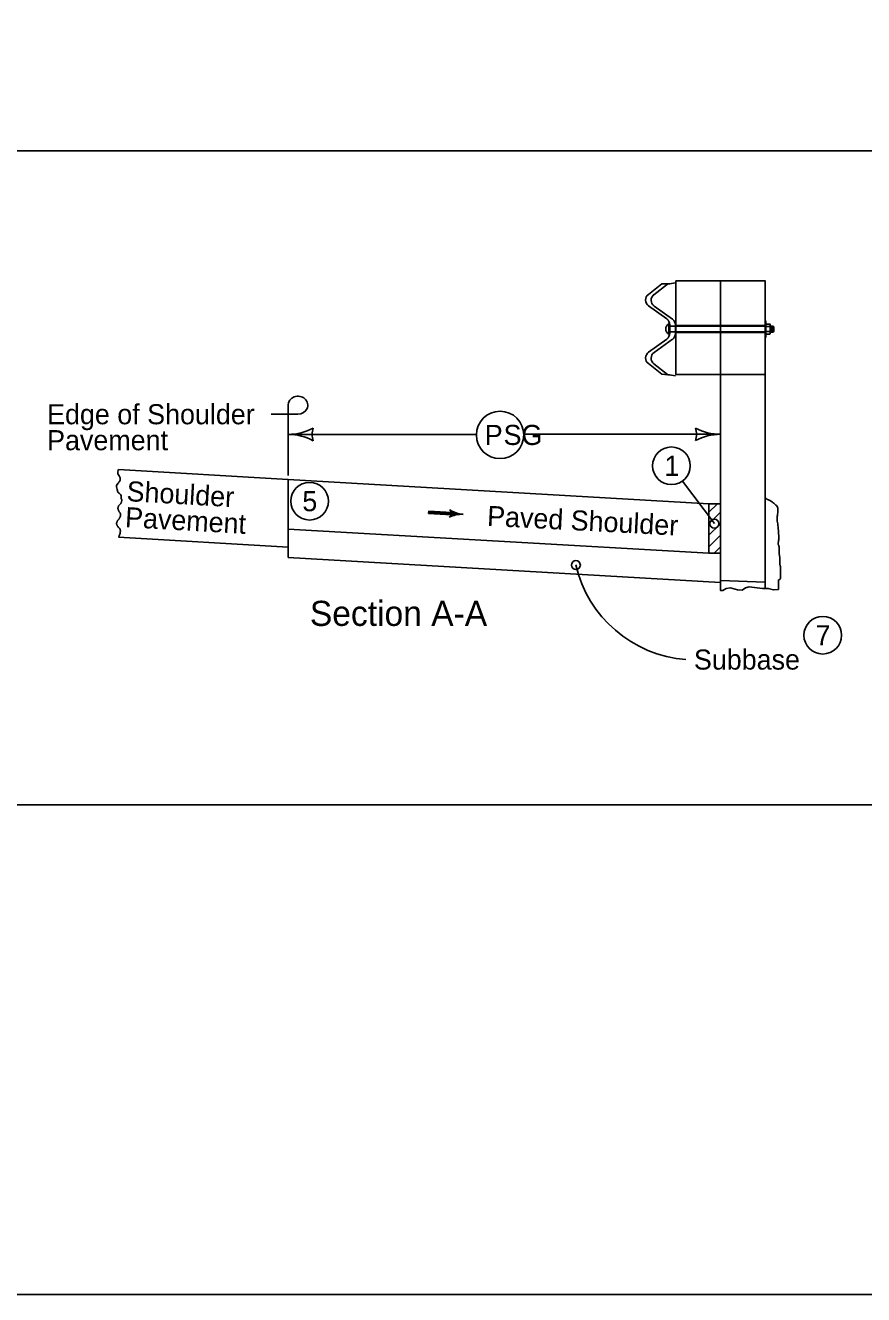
# Model space of a CAD drawing. Extents: x 8045 to 81668, y 6217 to 16762.
# Drawn here: x 10335 to 11002, y 7924 to 8935 of the extents above; entities that cross this region are included whole.
import ezdxf

# ---------------------------------------------------------------- set-up
doc = ezdxf.new("R2010")
doc.units = 0
for name, color, linetype in [('dsnStdDetailExtension', 7, 'Continuous'), ('dsnStdDimension', 7, 'Continuous'), ('dsnStdLabel', 7, 'Continuous'), ('dsnStdLineWork', 7, 'Continuous'), ('dsnStdPattern', 7, 'Continuous'), ('dsnStdSection', 7, 'Continuous'), ('Level 4', 7, 'Continuous'), ('Level 8', 7, 'Continuous'), ('TextBlockOut', 7, 'Continuous')]:
    doc.layers.add(name, color=color, linetype=linetype)

msp = doc.modelspace()

# ---------------------------------------------------------------- linework, layer by layer
at = {"layer": 'dsnStdDetailExtension'}
msp.add_circle((10773.3, 8505.4), 3.54, dxfattribs=at)
msp.add_circle((10773.3, 8505.4), 3.54, dxfattribs=at)
at = {"layer": 'dsnStdDimension'}
msp.add_line((10152.2, 8314.4), (13247.9, 8314.4), dxfattribs=at)
at = {"layer": 'dsnStdLabel'}
for p, q in [((10831, 8721.1), (10841.8, 8729.5)), ((10835.4, 8720.8), (10846.2, 8729.3)), ((10841.8, 8729.5), (10848.1, 8729.6)), ((10846.2, 8729.3), (10852.6, 8730.4)), ((10924.1, 8731.8), (10853, 8731.8)), ((10853, 8657.2), (10853, 8731.8)), ((10888.5, 8657.2), (10888.5, 8731.8)), ((10924.1, 8731.8), (10924.1, 8486.8)), ((10845.7, 8701.5), (10831.2, 8712)), ((10850.2, 8701.3), (10835.6, 8711.8)), ((10924.1, 8700.1), (10924.7, 8700.1)), ((10924.7, 8686.8), (10924.7, 8700.1)), ((10847.3, 8689.4), (10847.3, 8697.5)), ((10847.3, 8695.8), (10852.8, 8695.8)), ((10847.3, 8691.2), (10853, 8691.2)), ((10848.1, 8690.1), (10848.1, 8696.9)), ((10848.1, 8690.1), (10848.1, 8693.5)), ((10848.1, 8693.5), (10848.1, 8690.1)), ((10848.3, 8695.8), (10853, 8695.8)), ((10852.6, 8693.3), (10852.6, 8696.7)), ((10852.6, 8689.9), (10852.6, 8693.3)), ((10852.6, 8693.3), (10852.6, 8689.9)), ((10853, 8696.2), (10924.1, 8696.2)), ((10853, 8695.8), (10924.1, 8695.8)), ((10853, 8691.2), (10924.1, 8691.2)), ((10853, 8690.8), (10924.1, 8690.8)), ((10924.7, 8697.5), (10927.7, 8697.5)), ((10924.7, 8695.5), (10927.7, 8695.5)), ((10924.7, 8691.4), (10927.7, 8691.4)), ((10924.7, 8689.4), (10927.7, 8689.4)), ((10928.1, 8690.4), (10928.1, 8696.5)), ((10928.1, 8695.8), (10930.4, 8695.8)), ((10928.1, 8691.1), (10930.4, 8691.1)), ((10929, 8695.8), (10929, 8691.1)), ((10929.7, 8695.8), (10929.7, 8691.1)), ((10930.4, 8695.8), (10930.9, 8695.3)), ((10930.4, 8695.8), (10930.4, 8691.1)), ((10930.9, 8691.7), (10930.4, 8691.1)), ((10930.9, 8695.3), (10930.9, 8691.7)), ((10831.2, 8675.1), (10845.7, 8685.5)), ((10835.6, 8674.8), (10850.2, 8685.3)), ((10924.1, 8686.8), (10924.7, 8686.8)), ((10841.8, 8657.5), (10831, 8665.9)), ((10846.2, 8657.3), (10835.4, 8665.7)), ((10848.9, 8656.8), (10841.8, 8657.5)), ((10852.6, 8656.2), (10846.2, 8657.3)), ((10888.5, 8657.2), (10853, 8657.2)), ((10888.5, 8657.2), (10888.5, 8485)), ((10409, 8581.6), (10544.1, 8573.7)), ((10544.1, 8573.7), (10544.1, 8519.7)), ((10544.1, 8573.7), (10879.2, 8554.2)), ((10879.2, 8547.5), (10886, 8554.2)), ((10879.2, 8547.5), (10886, 8554.2)), ((10879.2, 8547.5), (10886, 8554.2)), ((10879.2, 8547.5), (10886, 8554.2)), ((10879.2, 8554.2), (10888.5, 8554.2)), ((10879.2, 8554.2), (10879.2, 8514.8)), ((10879.2, 8538.3), (10888.5, 8547.5)), ((10879.2, 8538.3), (10888.5, 8547.5)), ((10879.2, 8538.3), (10888.5, 8547.5)), ((10879.2, 8538.3), (10888.5, 8547.5)), ((10934.1, 8547.5), (10934.1, 8547.5)), ((10879.2, 8529.1), (10888.5, 8538.3)), ((10879.2, 8529.1), (10888.5, 8538.3)), ((10879.2, 8529.1), (10888.5, 8538.3)), ((10879.2, 8529.1), (10888.5, 8538.3)), ((10409, 8527.6), (10544.1, 8519.7)), ((10879.2, 8514.8), (10544.1, 8534.1)), ((10879.2, 8519.8), (10888.5, 8529.1)), ((10544.1, 8519.7), (10544.1, 8511.3)), ((10883.3, 8514.8), (10888.5, 8519.9)), ((10544.1, 8511.3), (10888.5, 8491.4)), ((10879.2, 8514.8), (10888.5, 8514.8))]:
    msp.add_line(p, q, dxfattribs=at)
for points in [[(10927.8, 8695.5), (10927.8, 8695.5), (10927.9, 8695.6), (10928, 8695.9), (10928, 8696.1), (10928, 8694.2), (10928, 8694.7), (10927.9, 8695.1), (10927.8, 8695.4), (10927.8, 8695.5), (10927.8, 8695.5), (10927.9, 8695.6), (10928, 8695.9), (10928, 8696), (10928, 8694.5), (10928, 8695), (10927.9, 8695.2), (10927.8, 8695.5), (10927.8, 8695.5), (10928, 8695.7), (10928, 8695.9), (10928, 8694.7), (10927.8, 8695.5), (10928, 8695.7), (10928, 8694.9), (10927.8, 8695.4), (10928, 8695.7), (10928, 8695), (10927.9, 8695.4), (10928, 8695.6), (10928, 8695.2), (10927.9, 8695.4), (10927.9, 8695.5), (10927.9, 8695.3), (10927.9, 8695.4), (10927.9, 8695.4)], [(10928, 8690.8), (10928, 8691), (10928, 8691.2), (10927.9, 8691.4), (10927.8, 8691.5), (10927.8, 8691.5), (10927.9, 8691.8), (10928, 8692.1), (10928.1, 8692.8), (10928, 8690.8), (10928, 8690.9), (10928, 8691.1), (10927.9, 8691.3), (10927.8, 8691.4), (10927.8, 8691.5), (10927.9, 8691.7), (10928, 8692.2), (10928, 8692.6), (10928, 8691), (10928, 8691.1), (10928, 8691.2), (10927.8, 8691.4), (10927.9, 8691.6), (10928, 8691.9), (10928, 8692.3), (10928, 8691.1), (10928, 8691.2), (10927.9, 8691.4), (10927.9, 8691.6), (10928, 8691.9), (10928, 8692.1), (10928, 8691.2), (10927.9, 8691.3), (10927.9, 8691.4), (10928, 8691.9), (10928, 8691.3), (10927.9, 8691.4), (10927.9, 8691.7), (10927.9, 8691.4), (10927.9, 8691.4), (10927.9, 8691.5), (10927.9, 8691.5)], [(10934.6, 8523.6), (10934.5, 8523.3), (10934.5, 8523.1), (10934.5, 8523), (10934.5, 8522.8), (10934.5, 8522.6), (10934.5, 8522.4), (10934.5, 8522.1), (10934.5, 8521.9), (10934.6, 8521.6), (10934.7, 8521.3), (10934.9, 8521.1), (10934.9, 8520.9), (10935, 8520.7), (10935, 8520.5), (10935, 8520.3), (10935.1, 8520.2), (10935.1, 8520), (10935.1, 8519.8), (10935.1, 8519.6), (10935.1, 8519.4), (10935.1, 8519.2), (10935.1, 8518.9), (10935.1, 8518.7), (10935.1, 8518.5), (10935.1, 8518.2), (10935.1, 8518), (10935.1, 8517.8), (10935.2, 8517.7), (10935.2, 8517.5), (10935.2, 8517.3), (10935.2, 8517.1), (10935.2, 8516.9), (10935.2, 8516.7), (10935.2, 8516.5), (10935.2, 8516.3), (10935.2, 8516.1), (10935.2, 8515.9), (10935.2, 8515.7), (10935.2, 8515.5), (10935.2, 8515.3), (10935.2, 8515.1), (10935.2, 8514.9), (10935.2, 8514.7), (10935.2, 8514.6), (10935.2, 8514.4), (10935.2, 8514.2), (10935.3, 8514.1), (10935.3, 8513.9), (10935.3, 8513.7), (10935.4, 8513.6), (10935.4, 8513.4), (10935.4, 8513.2), (10935.5, 8513.1), (10935.5, 8512.9), (10935.5, 8512.7), (10935.5, 8512.5), (10935.5, 8512.2), (10935.6, 8511.9), (10935.6, 8511.7), (10935.6, 8511.5), (10935.6, 8511.3), (10935.6, 8511.1), (10935.6, 8510.9), (10935.6, 8510.7), (10935.6, 8510.5), (10935.6, 8510.4), (10935.6, 8510.2), (10935.6, 8510), (10935.6, 8509.8), (10935.6, 8509.6), (10935.6, 8509.4), (10935.6, 8509.2), (10935.6, 8509), (10935.6, 8508.8), (10935.6, 8508.6), (10935.6, 8508.4), (10935.6, 8508.2), (10935.6, 8508), (10935.6, 8507.8), (10935.6, 8507.6), (10935.6, 8507.4), (10935.6, 8507.2), (10935.6, 8507), (10935.6, 8506.8), (10935.6, 8506.6), (10935.6, 8506.4), (10935.6, 8506.2), (10935.7, 8506.1), (10935.7, 8505.9), (10935.7, 8505.7), (10935.8, 8505.5), (10935.9, 8505.2), (10935.9, 8505), (10936, 8504.9), (10936, 8504.7), (10936.1, 8504.6), (10936.2, 8504.5), (10936.2, 8504.3), (10936.2, 8504.1), (10936.2, 8503.9), (10936.3, 8503.8), (10936.3, 8503.6), (10936.3, 8503.4), (10936.3, 8503.2), (10936.3, 8503), (10936.3, 8502.8), (10936.3, 8502.6), (10936.3, 8502.4), (10936.3, 8502.2), (10936.3, 8502), (10936.3, 8501.9), (10936.3, 8501.7), (10936.3, 8501.5), (10936.3, 8501.3), (10936.3, 8501.1), (10936.3, 8500.9), (10936.3, 8500.7), (10936.3, 8500.5), (10936.3, 8500.3), (10936.3, 8500.1), (10936.3, 8499.9), (10936.3, 8499.7), (10936.3, 8499.5), (10936.3, 8499.3), (10936.3, 8499.1), (10936.3, 8498.9), (10936.3, 8498.9), (10936.3, 8499.2), (10936.3, 8499.4), (10936.3, 8499.6), (10936.3, 8499.4), (10936.3, 8499.2), (10936.3, 8499), (10936.3, 8498.8), (10936.3, 8498.6), (10936.3, 8498.4), (10936.3, 8498.2), (10936.3, 8498), (10936.3, 8497.8), (10936.3, 8497.6), (10936.3, 8497.5), (10936.3, 8497.3), (10936.3, 8497.1), (10936.3, 8496.9), (10936.3, 8496.7), (10936.2, 8496.6), (10936.2, 8496.4), (10936.2, 8496.2), (10936.2, 8496), (10936.2, 8495.8), (10936.2, 8495.6), (10936.2, 8495.4), (10936.2, 8495.2), (10936.2, 8495), (10936.2, 8494.8), (10936.2, 8494.6), (10936.1, 8494.5), (10936, 8494.3), (10935.9, 8494.2), (10935.8, 8494.1), (10935.7, 8494), (10935.5, 8493.9), (10935.3, 8493.9), (10935.2, 8493.8), (10935.1, 8493.7), (10935, 8493.6), (10934.8, 8493.5), (10934.7, 8493.4), (10934.7, 8493.3), (10934.6, 8493.2), (10934.6, 8493), (10934.6, 8492.8), (10934.6, 8492.6), (10934.6, 8485.8)], [(10934.7, 8485.8), (10930.6, 8485.6), (10926.5, 8486.8), (10921.9, 8486.8), (10917.7, 8487.2), (10911.4, 8488), (10908.3, 8487.3), (10905.7, 8485.5), (10902, 8485.7), (10896.4, 8487.3), (10893.1, 8486.8), (10890.3, 8485.2), (10888.5, 8485)]]:
    msp.add_lwpolyline(points, dxfattribs=at)
for centre, radius, start, end in [((10834.5, 8716.6), 5.68, 127.75, 234.6909), ((10838.9, 8716.4), 5.68, 127.75, 234.6909), ((10842.4, 8696.9), 5.68, 360, 54.691), ((10846.9, 8696.7), 5.68, 360, 54.691), ((10849.4, 8693.5), 4.54, 117.2029, 242.8461), ((10842.4, 8690.1), 5.68, 305.309, 0), ((10846.9, 8689.9), 5.68, 305.309, 0), ((10834.5, 8670.4), 5.68, 125.3091, 232.25), ((10838.9, 8670.2), 5.68, 125.3091, 232.25)]:
    msp.add_arc(centre, radius, start, end, dxfattribs=at)
for centre in [(10927.7, 8696.5), (10927.7, 8690.4)]:
    msp.add_ellipse(centre, major_axis=(0, -1.01), ratio=0.362258, start_param=6.283156, end_param=9.424748, dxfattribs=at)
for points in [[(10409, 8581.6), (10408.5, 8578), (10409.5, 8576.5), (10410.4, 8574.2), (10409.8, 8572.1), (10407.9, 8569.7), (10407.3, 8567.8), (10407.9, 8565.5), (10408.7, 8563.2), (10409.8, 8562.4), (10411.2, 8559.9), (10411.1, 8559.1)], [(10409.2, 8542), (10409.4, 8542.2), (10409.6, 8542.5), (10409.9, 8543), (10410.2, 8543.6), (10410.3, 8543.9), (10410.4, 8544.2), (10410.6, 8544.9), (10410.6, 8545.5), (10410.6, 8546.1), (10410.5, 8546.3), (10410.5, 8546.5), (10410.4, 8546.6), (10410.2, 8547), (10409.9, 8547.4), (10409.6, 8547.7), (10409.4, 8548.1), (10409.3, 8548.4), (10409.1, 8548.7), (10408.9, 8549.3), (10408.7, 8549.8), (10408.6, 8550.1), (10408.5, 8550.4), (10408.5, 8550.5), (10408.5, 8550.7), (10408.7, 8551.4), (10408.9, 8552), (10409.1, 8552.5), (10409.6, 8553.1), (10410.1, 8553.7), (10410.6, 8554.2), (10410.8, 8554.5), (10411, 8554.8), (10411.2, 8555.3), (10411.4, 8555.8), (10411.5, 8556.3), (10411.5, 8556.5), (10411.6, 8556.6), (10411.6, 8556.7), (10411.5, 8557.3), (10411.4, 8557.8), (10411.3, 8557.9), (10411.3, 8558), (10411.2, 8558.2), (10411.2, 8558.3), (10411.1, 8559.1)], [(10934.6, 8523.6), (10934.9, 8526.5), (10934.7, 8531.4), (10934.2, 8537.1), (10933.6, 8541.6), (10933.8, 8544.9), (10934.2, 8549.1), (10933.6, 8552.2), (10931.4, 8554.2), (10929.4, 8555.9), (10927.2, 8557), (10924.9, 8558.4), (10924.1, 8559)], [(10409.2, 8542), (10409, 8541.7), (10408.7, 8541.5), (10408.5, 8541.2), (10408.3, 8541), (10408.2, 8540.7), (10408, 8540.4), (10407.8, 8539.8), (10407.7, 8539.6), (10407.6, 8539.3), (10407.5, 8539), (10407.5, 8538.8), (10407.4, 8538.7), (10407.4, 8538.2), (10407.6, 8537.7), (10407.8, 8537.1), (10408, 8536.6), (10408.5, 8536), (10409, 8535.4), (10409.5, 8534.9), (10409.8, 8534.6), (10410, 8534.2), (10410.4, 8533.3), (10410.5, 8532.8), (10410.5, 8532.3), (10410.4, 8532.1), (10410.4, 8531.8), (10410.3, 8531.5), (10410.3, 8531.2), (10410, 8530.1), (10409.8, 8529.4), (10409.6, 8528.8), (10409.4, 8528.3), (10409.2, 8528), (10409.1, 8527.7), (10409, 8527.6)]]:
    msp.add_spline(points, degree=3, dxfattribs=at)
at = {"layer": 'dsnStdLineWork'}
for p, q in [((10544.1, 8612.8), (10544.1, 8633.7)), ((10530.7, 8625.6), (10539.4, 8625.6)), ((10551.9, 8625.6), (10539.4, 8625.6)), ((10544.1, 8576.9), (10544.1, 8612.8)), ((10544.1, 8609.5), (10693.9, 8609.5)), ((10731.8, 8609.6), (10888.5, 8609.6)), ((10674.3, 8546.4), (10656.1, 8547.4)), ((10674.3, 8547.4), (10674.3, 8547.4)), ((10674.2, 8545.4), (10674.2, 8545.4))]:
    msp.add_line(p, q, dxfattribs=at)
for points in [[(10674.3, 8547.3), (10656.2, 8548.4), (10656, 8546.5), (10674.2, 8545.4), (10674.3, 8547), (10656.4, 8548.1), (10656.3, 8546.6), (10673.8, 8545.7), (10674, 8546.8), (10656.6, 8547.9), (10656.6, 8546.9), (10673.6, 8545.9), (10673.7, 8546.6), (10656.8, 8547.7), (10656.8, 8547.1), (10673.4, 8546.2)], [(10673.9, 8548.6), (10674.6, 8547.4), (10674.6, 8545.8), (10673.9, 8544.4), (10676.6, 8545.2), (10679.8, 8545.9), (10680.7, 8546), (10678.5, 8546.5), (10675.2, 8547.8), (10674.3, 8548.3), (10674.4, 8544.8), (10679.4, 8546), (10674.7, 8547.6), (10674.7, 8545.2), (10678.1, 8546.1), (10675.1, 8547), (10674.9, 8545.6), (10677.1, 8546.1), (10675.5, 8546.6), (10675.3, 8545.9), (10676.1, 8546.1)]]:
    msp.add_lwpolyline(points, dxfattribs=at)
msp.add_circle((10712.9, 8609.1), 18.9, dxfattribs=at)
for centre, radius, start, end in [((10544.1, 8652), 42.5, 270, 298.0725), ((10544.1, 8567), 42.5, 61.9275, 90), ((10579.7, 8609.5), 16.4, 162.2666, 197.7334), ((10852.9, 8609.6), 16.4, 342.2666, 17.7333), ((10888.5, 8652.1), 42.5, 241.9275, 270), ((10888.5, 8567.1), 42.5, 90, 118.0725), ((10868.5, 8527.6), 97.8, 193.077, 265.558)]:
    msp.add_arc(centre, radius, start, end, dxfattribs=at)
for centre, major_axis, start_param, end_param in [((10551.9, 8632.8), (-7.81, 0), 1.570796, 6.283185), ((10670.5, 8546.6), (3.88, 0), 5.202895, 7.237436), ((10685.6, 8566), (-22.2, 0), 0.954258, 1.478381), ((10682.8, 8525.6), (22.2, 0), 1.537172, 2.061295)]:
    msp.add_ellipse(centre, major_axis=major_axis, ratio=0.913811, start_param=start_param, end_param=end_param, dxfattribs=at)
at = {"layer": 'dsnStdPattern'}
for p, q in [((10831.2, 8712), (10845.7, 8701.5)), ((10845.7, 8685.5), (10831.2, 8675.1)), ((10879.2, 8554.2), (10544.1, 8573.7)), ((10544.1, 8573.7), (10544.1, 8534.1)), ((10879.2, 8514.8), (10879.2, 8554.2)), ((10544.1, 8534.1), (10879.2, 8514.8))]:
    msp.add_line(p, q, dxfattribs=at)
for points in [[(10835.5, 8720.9), (10835.4, 8720.8), (10846.2, 8729.3), (10848.1, 8729.6), (10841.8, 8729.5), (10831, 8721.1)], [(10888.5, 8696.2), (10888.5, 8731.8), (10853, 8731.8), (10853, 8696.2), (10853, 8696.2), (10888.5, 8696.2)], [(10924.1, 8696.2), (10924.1, 8700.2), (10924.1, 8731.8), (10888.5, 8731.8), (10888.5, 8696.2), (10924.1, 8696.2)], [(10850.2, 8701.3), (10850.2, 8701.3), (10835.6, 8711.8), (10835.7, 8711.7)], [(10848.1, 8696.9), (10848.1, 8695.8), (10852.6, 8695.8), (10852.6, 8696.7), (10852.6, 8696.7)], [(10852.6, 8689.9), (10852.6, 8689.9), (10852.6, 8691.2), (10848.1, 8691.2), (10848.1, 8690.1), (10848.1, 8691.2), (10848.1, 8691.2), (10848.1, 8690.1)], [(10853, 8695.8), (10853, 8691.2), (10853, 8691.2), (10888.5, 8691.2), (10888.5, 8695.8), (10853, 8695.8), (10853, 8695.8)], [(10853, 8690.8), (10853, 8657.2), (10888.5, 8657.2), (10888.5, 8690.8), (10853, 8690.8)], [(10924.1, 8691.2), (10924.1, 8695.8), (10888.5, 8695.8), (10888.5, 8691.2), (10924.1, 8691.2)], [(10924.1, 8657.2), (10924.1, 8686.8), (10924.1, 8690.8), (10888.5, 8690.8), (10888.5, 8657.2), (10924.1, 8657.2)], [(10835.7, 8674.8), (10835.6, 8674.8), (10850.2, 8685.3), (10850.2, 8685.2)], [(10831, 8665.9), (10841.8, 8657.5), (10848.9, 8656.8), (10846.2, 8657.3), (10835.4, 8665.7), (10835.5, 8665.7)], [(10924.1, 8491.9), (10924.1, 8657.2), (10888.5, 8657.2), (10888.5, 8554.2), (10888.5, 8547.5), (10888.5, 8547.5), (10888.5, 8547.5), (10888.5, 8538.3), (10888.5, 8538.3), (10888.5, 8538.3), (10888.5, 8529.2), (10888.5, 8529.2), (10888.5, 8529.2), (10888.5, 8522.2), (10888.5, 8493), (10924.1, 8491.9)], [(10924.1, 8491.9), (10888.5, 8493), (10888.5, 8485), (10890.3, 8485.2), (10893.1, 8486.8), (10896.4, 8487.3), (10902, 8485.7), (10905.7, 8485.5), (10908.3, 8487.3), (10911.4, 8488), (10917.7, 8487.2), (10921.9, 8486.8), (10924.1, 8486.8), (10924.1, 8491.9)]]:
    msp.add_lwpolyline(points, dxfattribs=at)
msp.add_lwpolyline([(10852.6, 8695.8), (10848.1, 8695.8), (10848.1, 8692.4), (10848.1, 8693.5), (10848.1, 8691.2), (10852.6, 8691.2)], close=True, dxfattribs=at)
for centre, start, end in [((10834.5, 8716.6), 127.75, 234.6909), ((10838.9, 8716.4), 127.75, 234.6909), ((10842.4, 8696.9), 0, 54.691), ((10846.9, 8696.7), 0, 54.691), ((10842.4, 8690.1), 305.309, 0), ((10846.9, 8689.9), 305.309, 0), ((10834.5, 8670.4), 125.3091, 232.25), ((10838.9, 8670.2), 125.3091, 232.25)]:
    msp.add_arc(centre, 5.68, start, end, dxfattribs=at)
at = {"layer": 'dsnStdSection'}
msp.add_lwpolyline([(10132.5, 9944), (13267.5, 9944), (13267.5, 7924), (10132.5, 7924)], close=True, dxfattribs=at)
at = {"layer": 'Level 4'}
for p, q in [((12307.8, 8835.4), (10152.2, 8835.4)), ((10883.6, 8538.4), (10858.2, 8572.3))]:
    msp.add_line(p, q, dxfattribs=at)
at = {"layer": 'Level 8'}
for centre, radius in [((10849.4, 8584.5), 15), ((10561.2, 8556.3), 15), ((10883.6, 8538.4), 3.58), ((10969.9, 8449.5), 15)]:
    msp.add_circle(centre, radius, dxfattribs=at)
at = {"layer": 'TextBlockOut'}
msp.add_circle((10561.2, 8556.3), 15, dxfattribs=at)

# ---------------------------------------------------------------- texts
at = {"layer": 'dsnStdLineWork'}
for s, height, p in [('Edge of Shoulder ', 16, (10352.1, 8617.6)), ('Pavement', 16, (10352.1, 8596.9)), ('P', 16, (10700.7, 8601.1)), ('SG', 16, (10715.7, 8601.1)), ('Section A-A', 20, (10561.4, 8456.9)), ('Subbase', 16, (10867.3, 8422.1))]:
    msp.add_text(s, height=height, dxfattribs=at).set_placement(p)
for s, rotation, p in [('Shoulder', 356.7346, (10415.1, 8556.4)), ('Pavement', 356.7346, (10413.9, 8535.7)), ('Paved Shoulder ', 357.0678, (10702.3, 8536.7))]:
    msp.add_text(s, height=16, rotation=rotation, dxfattribs=at).set_placement(p)
at = {"layer": 'Level 8'}
for s, p in [('1', (10843.8, 8576.5)), ('5', (10555.4, 8548.3)), ('7', (10964.2, 8441.5))]:
    msp.add_text(s, height=16, dxfattribs=at).set_placement(p)

doc.saveas('drawing.dxf')
